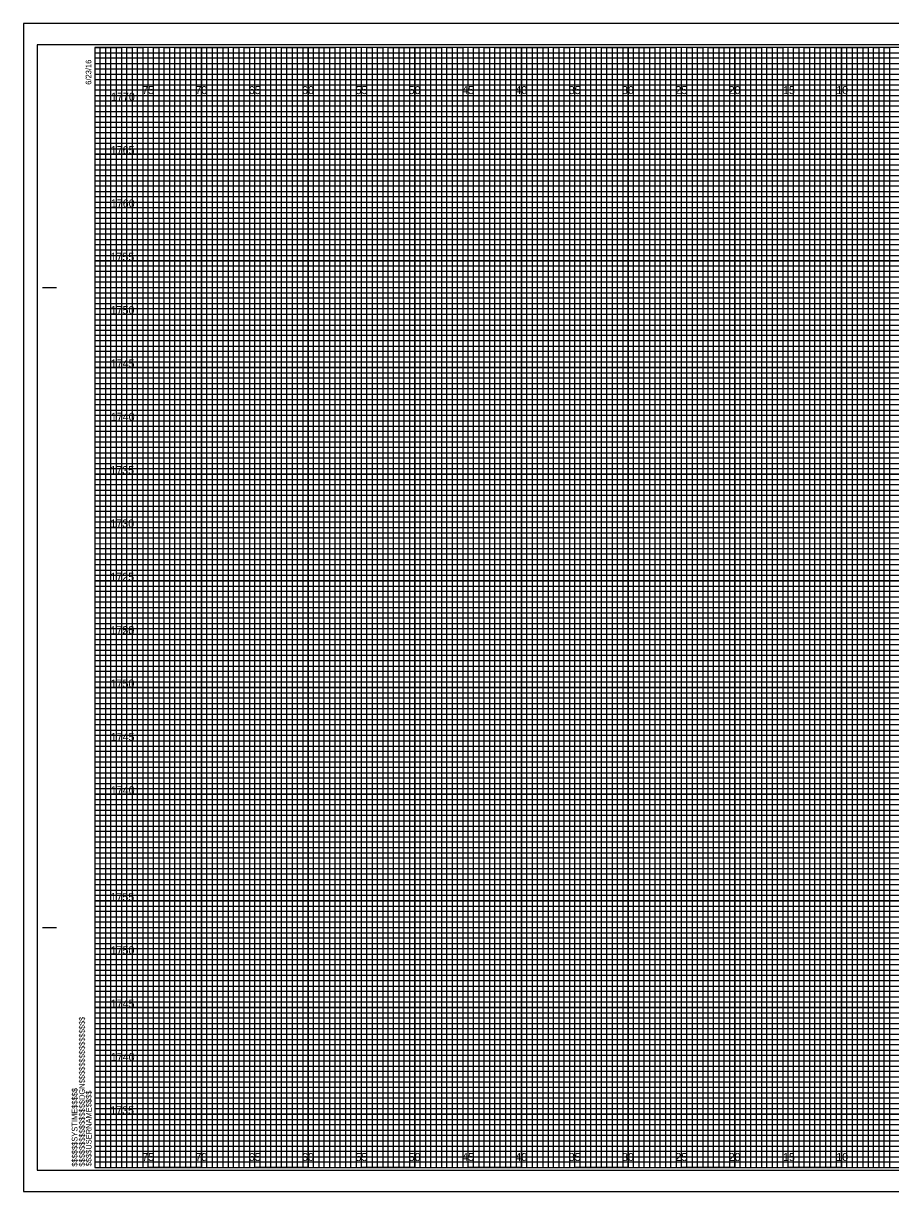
# Model space of a CAD drawing. Extents: x -7 to 162, y -2 to 547.
# Drawn here: x -6.7 to 74.6, y -2.3 to 107.3 of the extents above; entities that cross this region are included whole.
import ezdxf

# ---------------------------------------------------------------- set-up
doc = ezdxf.new("R2010")
doc.units = 0
for name, color, linetype in [('Prop XS Gore Control Minimum', 7, 'Continuous'), ('Prop XS Shoulder Borrow Shape', 7, 'Continuous'), ('Raster_Level_0', 7, 'Continuous'), ('Scratch_Level_3', 7, 'Continuous'), ('Sheet Cross Section CELL', 7, 'Continuous'), ('Sheet Cross Section Grid Minor 1 CELL', 7, 'Continuous'), ('Sheet Cross Section Grid Minor 2 CELL', 7, 'Continuous'), ('Sheet Cutting Line CELL', 7, 'Continuous'), ('Sheet DOT Grid CELL', 7, 'Continuous'), ('Sheet Plot Border Inside CELL', 7, 'Continuous'), ('Sheet Plot Border Outside CELL', 7, 'Continuous')]:
    doc.layers.add(name, color=color, linetype=linetype)

msp = doc.modelspace()

# ---------------------------------------------------------------- linework, layer by layer
at = {"layer": 'Prop XS Gore Control Minimum'}
for p, q in [((5, 105), (0, 105)), ((5, 0), (5, 105)), ((15, 105), (10, 105)), ((10, 105), (10, 0)), ((15, 0), (15, 105)), ((25, 105), (20, 105)), ((20, 105), (20, 0)), ((25, 0), (25, 105)), ((35, 105), (30, 105)), ((30, 105), (30, 0)), ((35, 0), (35, 105)), ((45, 105), (40, 105)), ((40, 105), (40, 0)), ((45, 0), (45, 105)), ((55, 105), (50, 105)), ((50, 105), (50, 0)), ((55, 0), (55, 105)), ((65, 105), (60, 105)), ((60, 105), (60, 0)), ((65, 0), (65, 105)), ((75, 105), (70, 105)), ((70, 105), (70, 0)), ((10, 0), (5, 0)), ((20, 0), (15, 0)), ((30, 0), (25, 0)), ((40, 0), (35, 0)), ((50, 0), (45, 0)), ((60, 0), (55, 0)), ((70, 0), (65, 0))]:
    msp.add_line(p, q, dxfattribs=at)
for points in [[(0, 100), (160, 100), (160, 95), (0, 95)], [(0, 90), (160, 90), (160, 85), (0, 85)], [(0, 80), (160, 80), (160, 75), (0, 75)], [(0, 70), (160, 70), (160, 65), (0, 65)], [(0, 60), (160, 60), (160, 55), (0, 55)], [(0, 50), (160, 50), (160, 45), (0, 45)], [(0, 40), (160, 40), (160, 35), (0, 35)], [(0, 30), (160, 30), (160, 25), (0, 25)], [(0, 20), (160, 20), (160, 15), (0, 15)], [(0, 10), (160, 10), (160, 5), (0, 5)]]:
    msp.add_lwpolyline(points, dxfattribs=at)
at = {"layer": 'Prop XS Shoulder Borrow Shape'}
for points in [[(0, 105), (2.5, 105), (2.5, 0), (7.5, 0), (7.5, 105), (12.5, 105), (12.5, 0), (17.5, 0), (17.5, 105), (22.5, 105), (22.5, 0), (27.5, 0), (27.5, 105), (32.5, 105), (32.5, 0), (37.5, 0), (37.5, 105), (42.5, 105), (42.5, 0), (47.5, 0), (47.5, 105), (52.5, 105), (52.5, 0), (57.5, 0), (57.5, 105), (62.5, 105), (62.5, 0), (67.5, 0), (67.5, 105), (72.5, 105), (72.5, 0), (77.5, 0)], [(0, 102.5), (137.5, 102.5)], [(0, 92.5), (160, 92.5), (160, 97.5), (0, 97.5)], [(0, 82.5), (160, 82.5), (160, 87.5), (0, 87.5)], [(0, 72.5), (160, 72.5), (160, 77.5), (0, 77.5)], [(0, 62.5), (160, 62.5), (160, 67.5), (0, 67.5)], [(0, 52.5), (160, 52.5), (160, 57.5), (0, 57.5)], [(0, 42.5), (160, 42.5), (160, 47.5), (0, 47.5)], [(0, 32.5), (160, 32.5), (160, 37.5), (0, 37.5)], [(0, 22.5), (160, 22.5), (160, 27.5), (0, 27.5)], [(0, 12.5), (160, 12.5), (160, 17.5), (0, 17.5)], [(0, 2.5), (160, 2.5), (160, 7.5), (0, 7.5)]]:
    msp.add_lwpolyline(points, dxfattribs=at)
at = {"layer": 'Sheet Cross Section CELL'}
for p, q in [((-4.9, 82.5), (-3.65, 82.5)), ((-4.85, 82.5), (-3.6, 82.5)), ((-4.9, 22.5), (-3.65, 22.5)), ((-4.85, 22.5), (-3.6, 22.5)), ((0, 0), (0, 0)), ((0, 0), (0, 0)), ((0, 0), (0, 0)), ((0, 0), (0, 0)), ((0, 0), (0, 0)), ((0, 0), (0, 0)), ((0, 0), (0, 0))]:
    msp.add_line(p, q, dxfattribs=at)
msp.add_lwpolyline([(160, 105), (0, 105), (0, 0), (160, 0)], close=True, dxfattribs=at)
at = {"layer": 'Sheet Cross Section Grid Minor 1 CELL'}
for p, q in [((0, 104.5), (130, 104.5)), ((130, 103.99), (0, 103.99)), ((0, 103.99), (0, 103.5)), ((0, 103.5), (130, 103.5)), ((130, 102.95), (0, 102.95)), ((0, 102.95), (0, 102)), ((0, 102), (160, 102))]:
    msp.add_line(p, q, dxfattribs=at)
for points in [[(0, 101.5), (135, 101.5), (160, 101.5), (160, 101), (0, 101)], [(0, 100.5), (160, 100.5), (160, 99.5), (0, 99.5)], [(0, 99), (160, 99), (160, 98.5), (0, 98.49)], [(0, 98), (160, 98), (160, 97), (0, 97)], [(0, 96.5), (160, 96.5), (160, 96), (0, 96)], [(0, 95.5), (160, 95.5), (160, 94.5), (0, 94.5)], [(0, 94), (160, 94), (160, 93.5), (0, 93.5)], [(0, 93), (160, 93), (160, 92), (0, 92)], [(0, 91.5), (160, 91.5), (160, 91), (0, 91)], [(0, 90.5), (160, 90.5), (160, 89.5), (0, 89.5)], [(0, 89), (160, 89), (160, 88.5), (0, 88.5)], [(0, 88), (160, 88), (160, 86.98), (160, 86.5), (160, 86), (0, 86)], [(0, 87), (160, 87), (160, 86.5), (0, 86.5)], [(0, 85.5), (160, 85.5), (160, 84.5), (0, 84.52)], [(0, 84.52), (160, 84.5), (160, 84), (0, 84)], [(0, 83.5), (160, 83.5), (160, 83), (0, 83)], [(0, 82), (160, 82), (160, 81.5), (0, 81.5)], [(0, 81), (160, 81), (160, 80.5), (0, 80.5)], [(-0.04, 79.45), (160, 79.45), (160, 78.94), (-0.04, 78.94)], [(0, 78.5), (160, 78.5), (160, 78), (0, 78)], [(0, 77), (160, 77), (160, 76.5), (0, 76.5)], [(0, 76), (160, 76), (160, 75.5), (0, 75.5)], [(0, 74.5), (160, 74.5), (160, 74), (0, 74)], [(0, 73.5), (160, 73.5), (160, 73), (0, 73)], [(0, 72), (160, 72), (160, 71.5), (0, 71.5)], [(0, 71), (160, 71), (160, 70.5), (0, 70.5)], [(0, 69.5), (160, 69.5), (160, 68.99), (0, 69)], [(0, 68.5), (160, 68.5), (160, 68), (0, 68)], [(0, 67), (160, 67), (160, 66.5), (0, 66.5)], [(0, 66), (160, 66), (160, 65.5), (0, 65.5)], [(0, 64.5), (160, 64.5), (160, 64), (0, 64)], [(0, 63.5), (160, 63.5), (160, 63), (0, 63)], [(0, 62), (160, 62), (160, 61.5), (0, 61.5)], [(0, 61), (160, 61), (160, 60.5), (0, 60.5)], [(0, 59.5), (160, 59.5), (160, 59), (0, 59)], [(0, 58.5), (160.03, 58.45), (160, 58), (0, 58)], [(0, 57), (160, 57), (160, 56.5), (0, 56.5)], [(0, 56), (160, 56), (160, 55.5), (0, 55.5)], [(0, 54.5), (160, 54.5), (160, 54), (0, 54)], [(0, 53.5), (160, 53.5), (160, 53), (0, 53)], [(0, 52), (160, 52), (160, 51.5), (0, 51.5)], [(0, 51), (160, 51), (160, 50.5), (0, 50.5)], [(0, 49.5), (160, 49.5), (160, 49), (0, 49)], [(0, 48.5), (160, 48.5), (160, 48), (0, 48)], [(0, 47), (160, 47), (160, 46.5), (0, 46.5)], [(0, 46), (160, 46), (160, 45.5), (0, 45.5)], [(0, 44.5), (160, 44.5), (160, 44), (0, 44)], [(0, 43.5), (160, 43.5), (160, 43), (0, 43)], [(0, 42), (160, 42), (160, 41.5), (0, 41.5)], [(0, 41), (160, 41), (160, 40.5), (0, 40.5)], [(0, 39.5), (160, 39.5), (160, 38.99), (0, 39)], [(0, 38.5), (160, 38.5), (160, 38), (0, 38)], [(0, 37), (160, 37), (160, 36.5), (0, 36.5)], [(0, 36), (160, 36), (160, 35.5), (0, 35.5)], [(0, 34.5), (160, 34.5), (160, 34), (0, 34)], [(0, 33.5), (160, 33.5), (160, 33), (0, 33)], [(0, 32), (160, 32), (160, 31.5), (0, 31.5)], [(0, 31), (160, 31), (160, 30.5), (0, 30.5)], [(0, 29.5), (160, 29.5), (160, 29), (0, 29)], [(0, 28.5), (160.03, 28.46), (160, 28), (0, 28)], [(0, 27), (160, 27), (160, 26.5), (0, 26.5)], [(0, 26), (160, 26), (160, 25.5), (0, 25.5)], [(0, 24.5), (160, 24.5), (160, 24), (0, 24)], [(0, 23.5), (160, 23.5), (160, 23), (0, 23)], [(0, 22), (160, 22), (160, 21.5), (0, 21.5)], [(0, 21), (160, 21), (160, 20.5), (0, 20.5)], [(0, 19.5), (160, 19.5), (160, 19), (0, 19)], [(0, 18.5), (160, 18.5), (160, 18), (0, 18)], [(0, 17), (160, 17), (160, 16.5), (0, 16.5)], [(0, 16), (160, 16), (160, 15.5), (0, 15.5)], [(0, 14.5), (160, 14.5), (160, 14), (0, 14)], [(0, 13.5), (160, 13.5), (160, 13), (0, 13)], [(0, 12), (160, 12), (160, 11.5), (0, 11.5)], [(0, 11), (160, 11), (160, 10.5), (0, 10.5)], [(0, 9.5), (160, 9.5), (160, 9), (0, 9)], [(0, 8.5), (160, 8.5), (160, 8), (0, 8)], [(0, 7), (160, 7), (160, 6.5), (0, 6.5)], [(0, 6), (160, 6), (160, 5.5), (0, 5.5)], [(0, 4.5), (160, 4.5), (160, 4), (0, 4)], [(0, 3.5), (160, 3.5), (160, 3), (0, 3)], [(0, 2), (160, 2), (160, 1.5), (0, 1.5)], [(0, 1), (160, 1), (160, 0.5), (0, 0.5)]]:
    msp.add_lwpolyline(points, dxfattribs=at)
at = {"layer": 'Sheet Cross Section Grid Minor 2 CELL'}
for points in [[(0, 0), (0.5, 0), (0.5, 105), (1, 105), (1, 0)], [(1, 0), (1.5, 0), (1.5, 105), (2, 105), (2, 0)], [(2.5, 0), (3, 0), (3, 105), (3.5, 105), (3.5, 0)], [(3.5, 0), (4, 0), (4, 105), (4.5, 105), (4.5, 0)], [(5, 0), (5.5, 0), (5.5, 105), (6, 105), (6, 0)], [(6, 0), (6.5, 0), (6.5, 105), (7, 105), (7, 0)], [(7.5, 0), (8, 0), (8, 105), (8.5, 105), (8.5, 0)], [(8.5, 0), (9, 0), (9, 105), (9.5, 105), (9.5, 0)], [(10, 0), (10.5, 0), (10.5, 105), (11, 105), (11, 0)], [(11, 0), (11.5, 0), (11.5, 105), (12, 105), (12, 0)], [(12.5, 0), (13, 0), (13, 105), (13.5, 105), (13.5, 0)], [(13.5, 0), (14, 0), (14, 105), (14.5, 105), (14.5, 0)], [(15, 0), (15.5, 0), (15.5, 105), (16, 105), (16, 0)], [(16, 0), (16.5, 0), (16.5, 105), (17, 105), (17, 0)], [(17.5, 0), (18, 0), (18, 105), (18.5, 105), (18.5, 0)], [(18.5, 0), (19, 0), (19, 105), (19.5, 105), (19.5, 0)], [(20, 0), (20.5, 0), (20.5, 105), (21, 105), (21, 0)], [(21, 0), (21.5, 0), (21.5, 105), (22, 105), (22, 0)], [(22.5, 0), (23, 0), (23, 105), (23.5, 105), (23.5, 0)], [(23.5, 0), (24, 0), (24, 105), (24.5, 105), (24.5, 0)], [(25, 0), (25.5, 0), (25.5, 105), (26, 105), (26, 0)], [(26, 0), (26.5, 0), (26.5, 105), (27, 105), (27, 0)], [(27.5, 0), (28, 0), (28, 105), (28.5, 105), (28.5, 0)], [(28.5, 0), (29, 0), (29, 105), (29.5, 105), (29.5, 0)], [(30, 0), (30.5, 0), (30.5, 105), (31, 105), (31, 0)], [(31, 0), (31.5, 0), (31.5, 105), (32, 105), (32, 0)], [(32.5, 0), (33, 0), (33, 105), (33.5, 105), (33.5, 0)], [(33.5, 0), (34, 0), (34, 105), (34.5, 105), (34.5, 0)], [(35, 0), (35.5, 0), (35.5, 105), (36, 105), (36, 0)], [(36, 0), (36.5, 0), (36.5, 105), (37, 105), (37, 0)], [(37.5, 0), (38, 0), (38, 105), (38.5, 105), (38.5, 0)], [(38.5, 0), (39, 0), (39, 105), (39.5, 105), (39.5, 0)], [(40, 0), (40.5, 0), (40.5, 105), (41, 105), (41, 0)], [(41, 0), (41.5, 0), (41.5, 105), (42, 105), (42, 0)], [(42.5, 0), (43, 0), (43, 105), (43.5, 105), (43.5, 0)], [(43.5, 0), (44, 0), (44, 105), (44.5, 105), (44.5, 0)], [(45, 0), (45.5, 0), (45.5, 105), (46, 105), (46, 0)], [(46, 0), (46.5, 0), (46.5, 105), (47, 105), (47, 0)], [(47.5, 0), (48, 0), (48, 105), (48.5, 105), (48.5, 0)], [(48.5, 0), (49, 0), (49, 105), (49.5, 105), (49.5, 0)], [(50, 0), (50.5, 0), (50.5, 105), (51, 105), (51, 0)], [(51, 0), (51.5, 0), (51.5, 105), (52, 105), (52, 0)], [(52.5, 0), (53, 0), (53, 105), (53.5, 105), (53.5, 0)], [(53.5, 0), (54, 0), (54, 105), (54.5, 105), (54.5, 0)], [(55, 0), (55.5, 0), (55.5, 105), (56, 105), (56, 0)], [(56, 0), (56.5, 0), (56.5, 105), (57, 105), (57, 0)], [(57.5, 0), (58, 0), (58, 105), (58.5, 105), (58.5, 0)], [(58.5, 0), (59, 0), (59, 105), (59.5, 105), (59.5, 0)], [(60, 0), (60.5, 0), (60.5, 105), (61, 105), (61, 0)], [(61, 0), (61.5, 0), (61.5, 105), (62, 105), (62, 0)], [(62.5, 0), (63, 0), (63, 105), (63.5, 105), (63.5, 0)], [(63.5, 0), (64, 0), (64, 105), (64.5, 105), (64.5, 0)], [(65, 0), (65.5, 0), (65.5, 105), (66, 105), (66, 0)], [(66, 0), (66.5, 0), (66.5, 105), (67, 105), (67, 0)], [(67.5, 0), (68, 0), (68, 105), (68.5, 105), (68.5, 0)], [(68.5, 0), (69, 0), (69, 105), (69.5, 105), (69.5, 0)], [(70, 0), (70.5, 0), (70.5, 105), (71, 105), (71, 0)], [(71, 0), (71.5, 0), (71.5, 105), (72, 105), (72, 0)], [(72.5, 0), (73, 0), (73, 105), (73.5, 105), (73.5, 0)], [(73.5, 0), (74, 0), (74, 105), (74.5, 105), (74.5, 0)]]:
    msp.add_lwpolyline(points, dxfattribs=at)
at = {"layer": 'Sheet Cutting Line CELL'}
for p, q in [((161.65, 107.25), (-6.7, 107.25)), ((-6.7, 107.25), (-6.7, -2.25)), ((-6.7, -2.25), (161.65, -2.25))]:
    msp.add_line(p, q, dxfattribs=at)
at = {"layer": 'Sheet DOT Grid CELL'}
for p, q in [((5, 0), (5, 105)), ((10, 0), (10, 105)), ((15, 0), (15, 105)), ((20, 0), (20, 105)), ((25, 0), (25, 105)), ((30, 0), (30, 105)), ((35, 0), (35, 105)), ((40, 0), (40, 105)), ((45, 0), (45, 105)), ((50, 0), (50, 105)), ((55, 0), (55, 105)), ((60, 0), (60, 105)), ((65, 0), (65, 105)), ((70, 0), (70, 105)), ((0, 100), (160, 100)), ((0, 95), (160, 95)), ((0, 90), (160, 90)), ((0, 85), (160, 85)), ((0, 80), (160, 80)), ((0, 75), (160, 75)), ((0, 70), (160, 70)), ((0, 65), (160, 65)), ((0, 60), (160, 60)), ((0, 55), (160, 55)), ((0, 50), (160, 50)), ((0, 45), (160, 45)), ((0, 40), (160, 40)), ((0, 35), (160, 35)), ((0, 30), (160, 30)), ((0, 25), (160, 25)), ((0, 20), (160, 20)), ((0, 15), (160, 15)), ((0, 10), (160, 10)), ((0, 5), (160, 5))]:
    msp.add_line(p, q, dxfattribs=at)
at = {"layer": 'Sheet Plot Border Inside CELL'}
msp.add_lwpolyline([(-5.4, -0.25), (161.2, -0.25), (161.2, 105.25), (-5.4, 105.25)], close=True, dxfattribs=at)
at = {"layer": 'Sheet Plot Border Outside CELL'}
msp.add_lwpolyline([(-6.7, -2.25), (161.65, -2.25), (161.65, 107.25), (-6.7, 107.25)], close=True, dxfattribs=at)

# ---------------------------------------------------------------- texts
at = {"layer": 'Raster_Level_0'}
for s, p in [('75', (4.44, 100.62)), ('70', (9.43, 100.62)), ('65', (14.44, 100.62)), ('60', (19.43, 100.62)), ('55', (24.44, 100.62)), ('50', (29.43, 100.62)), ('45', (34.44, 100.62)), ('40', (39.43, 100.62)), ('35', (44.44, 100.62)), ('30', (49.43, 100.62)), ('25', (54.44, 100.62)), ('20', (59.43, 100.62)), ('15', (64.53, 100.62)), ('10', (69.52, 100.62)), ('75', (4.44, 0.62)), ('70', (9.43, 0.62)), ('65', (14.44, 0.62)), ('60', (19.43, 0.62)), ('55', (24.44, 0.62)), ('50', (29.43, 0.62)), ('45', (34.44, 0.62)), ('40', (39.43, 0.62)), ('35', (44.44, 0.62)), ('30', (49.43, 0.62)), ('25', (54.44, 0.62)), ('20', (59.43, 0.62)), ('15', (64.53, 0.62)), ('10', (69.52, 0.62))]:
    msp.add_text(s, height=0.75, dxfattribs=at).set_placement(p)
at = {"layer": 'Scratch_Level_3'}
for s, p in [('1770', (1.52, 100)), ('1765', (1.49, 95)), ('1760', (1.5, 90)), ('1755', (1.47, 85)), ('1750', (1.48, 80)), ('1745', (1.49, 75)), ('1740', (1.5, 70)), ('1735', (1.45, 65)), ('1730', (1.46, 60)), ('1725', (1.46, 55)), ('1720', (1.47, 50)), ('1755', (1.47, 50)), ('1750', (1.48, 45)), ('1745', (1.49, 40)), ('1740', (1.5, 35)), ('1755', (1.47, 25)), ('1750', (1.48, 20)), ('1745', (1.49, 15)), ('1740', (1.5, 10)), ('1735', (1.45, 5))]:
    msp.add_text(s, height=0.75, dxfattribs=at).set_placement(p)
at = {"layer": 'Sheet Cross Section CELL'}
for s, p in [('6/23/16', (-0.33, 101.5)), ('$$$$$$$$$$$$$$$$DGN$$$$$$$$$$$$$$$$', (-0.94, 0.09)), ('$$$$$$SYSTIME$$$$$', (-1.63, 0.09)), ('$$$$USERNAME$$$$', (-0.31, 0.12))]:
    msp.add_text(s, height=0.525, rotation=90, dxfattribs=at).set_placement(p)

doc.saveas('drawing.dxf')
